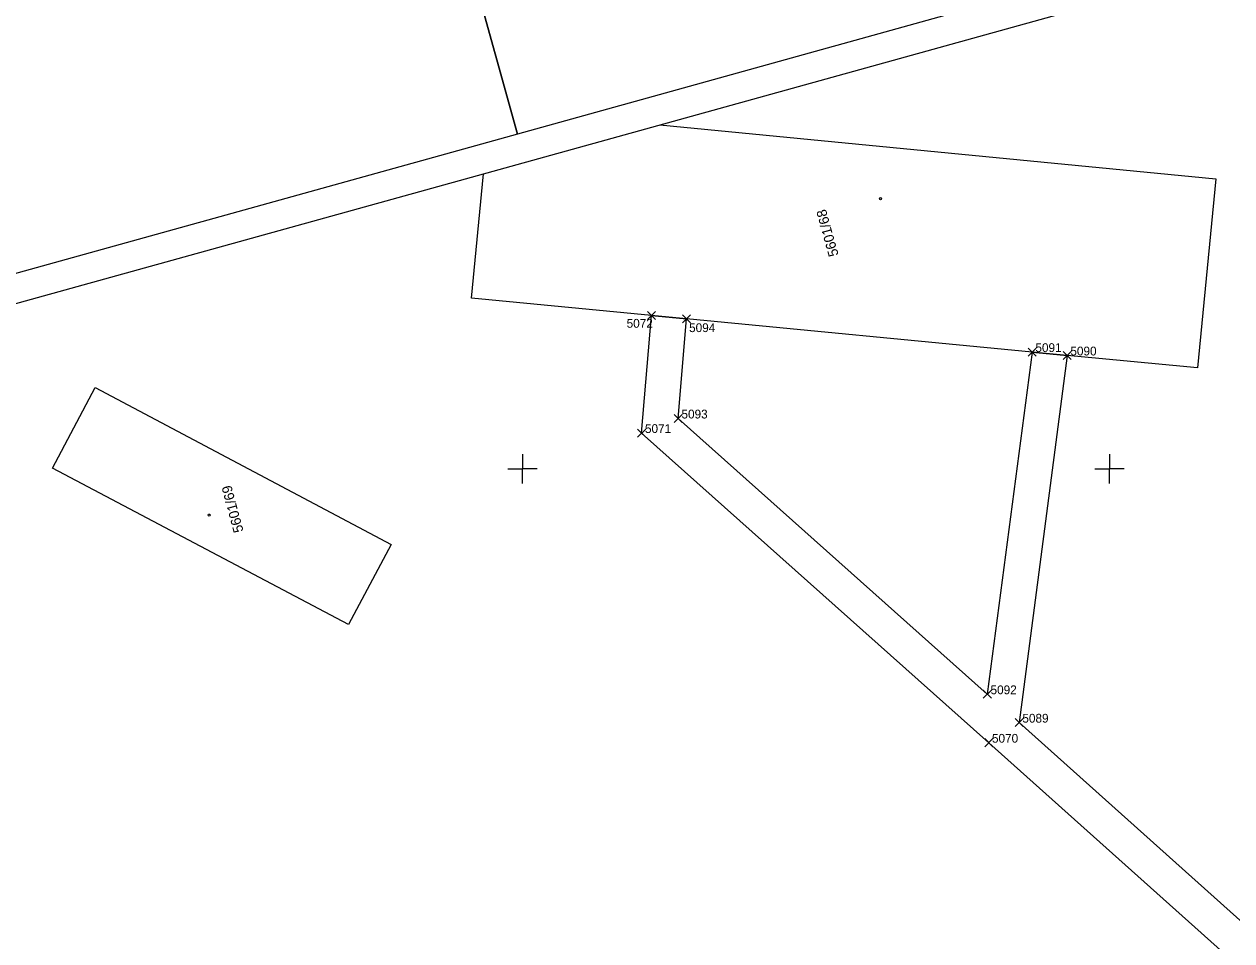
# Model space of a CAD drawing. Extents: x -821172 to -820632, y -1070921 to -1069931.
# Drawn here: x -821042.4 to -820939.6, y -1070140.2 to -1070062.1 of the extents above; entities that cross this region are included whole.
import ezdxf

# ---------------------------------------------------------------- set-up
doc = ezdxf.new("R2010")
doc.units = 0
for name, color, linetype in [('Ram', 7, 'Continuous'), ('Sit', 7, 'Continuous'), ('VB_bod_DZ', 7, 'Continuous'), ('Vrstva 52', 7, 'Continuous'), ('Vrstva 55', 7, 'Continuous'), ('Vrstva 57', 7, 'Continuous'), ('Vrstva 59', 7, 'Continuous')]:
    doc.layers.add(name, color=color, linetype=linetype)

msp = doc.modelspace()

# ---------------------------------------------------------------- linework, layer by layer
at = {"layer": 'Ram'}
msp.add_line((-820859.09, -1070034.8), (-821140.43, -1070112.97), dxfattribs=at)
for points in [[(-821000.43, -1070071.48), (-821028.54, -1069970.31), (-820885.46, -1069930.55), (-820857.35, -1070031.72)], [(-821028.54, -1069970.31), (-821000.43, -1070071.48)], [(-820857.35, -1070031.72), (-821000.43, -1070071.48)], [(-821000.43, -1070071.48), (-821143.51, -1070111.23)]]:
    msp.add_lwpolyline(points, dxfattribs=at)
at = {"layer": 'Sit'}
for p, q in [((-821000, -1070098.75), (-821000, -1070100)), ((-820950, -1070098.75), (-820950, -1070100)), ((-821001.25, -1070100), (-821000, -1070100)), ((-820998.75, -1070100), (-821000, -1070100)), ((-821000, -1070101.25), (-821000, -1070100)), ((-820951.25, -1070100), (-820950, -1070100)), ((-820948.75, -1070100), (-820950, -1070100)), ((-820950, -1070101.25), (-820950, -1070100))]:
    msp.add_line(p, q, dxfattribs=at)
at = {"layer": 'VB_bod_DZ'}
for p, q in [((-820989.35, -1070087.28), (-820988.66, -1070086.6)), ((-820988.66, -1070087.28), (-820989.35, -1070086.6)), ((-820986.36, -1070087.57), (-820985.68, -1070086.88)), ((-820985.68, -1070087.57), (-820986.36, -1070086.88)), ((-820956.93, -1070090.39), (-820956.24, -1070089.71)), ((-820956.24, -1070090.39), (-820956.93, -1070089.71)), ((-820953.94, -1070090.68), (-820953.25, -1070089.99)), ((-820953.25, -1070090.68), (-820953.94, -1070089.99)), ((-820987.07, -1070096.05), (-820986.39, -1070095.37)), ((-820986.39, -1070096.05), (-820987.07, -1070095.37)), ((-820990.19, -1070097.29), (-820989.5, -1070096.61)), ((-820989.5, -1070097.29), (-820990.19, -1070096.61)), ((-820960.74, -1070119.55), (-820960.05, -1070118.87)), ((-820960.05, -1070119.55), (-820960.74, -1070118.87)), ((-820958.03, -1070121.97), (-820957.34, -1070121.28)), ((-820957.34, -1070121.97), (-820958.03, -1070121.28)), ((-820960.62, -1070123.68), (-820959.93, -1070122.99)), ((-820959.93, -1070123.68), (-820960.62, -1070122.99))]:
    msp.add_line(p, q, dxfattribs=at)
at = {"layer": 'Vrstva 52'}
for p, q in [((-820989.01, -1070086.94), (-820986.02, -1070087.23)), ((-820956.59, -1070090.05), (-820960.4, -1070119.21)), ((-820956.59, -1070090.05), (-820953.6, -1070090.34)), ((-820953.6, -1070090.34), (-820957.69, -1070121.63))]:
    msp.add_line(p, q, dxfattribs=at)
for points in [[(-820843.48, -1070284.13), (-820843.93, -1070282.84), (-820847.81, -1070277.93), (-820871.73, -1070237.25), (-820885.29, -1070218.2), (-820887.54, -1070214.67), (-820897.96, -1070197.77), (-820903.32, -1070188.38), (-820912.12, -1070190.61), (-820919.97, -1070176.29), (-820926.49, -1070162.4), (-820934.28, -1070147.4), (-820935.96, -1070145.11), (-820960.28, -1070123.34), (-820989.85, -1070096.95), (-820989.01, -1070086.94)], [(-820960.4, -1070119.21), (-820986.73, -1070095.71), (-820986.02, -1070087.23)], [(-820905.06, -1070185.73), (-820910.61, -1070187.13), (-820917.29, -1070174.93), (-820923.8, -1070161.07), (-820931.72, -1070145.81), (-820933.72, -1070143.08), (-820957.69, -1070121.63)]]:
    msp.add_lwpolyline(points, dxfattribs=at)
at = {"layer": 'Vrstva 55'}
for points in [[(-820988.3, -1070070.68), (-820940.94, -1070075.3), (-820942.5, -1070091.4)], [(-820942.5, -1070091.4), (-820953.6, -1070090.34), (-820956.59, -1070090.05), (-820986.02, -1070087.23), (-820989.01, -1070086.94), (-821004.34, -1070085.47), (-821003.31, -1070074.87)], [(-821014.82, -1070113.27), (-821040.04, -1070099.95), (-821036.4, -1070093.07), (-821011.18, -1070106.44), (-821014.82, -1070113.27)]]:
    msp.add_lwpolyline(points, dxfattribs=at)
at = {"layer": 'Vrstva 59'}
for centre in [(-820969.49, -1070076.98), (-821026.69, -1070103.94)]:
    msp.add_circle(centre, 0.0875, dxfattribs=at)

# ---------------------------------------------------------------- texts
at = {"layer": 'VB_bod_DZ'}
for s, p in [(' 5072', (-820991.4, -1070087.98)), (' 5094', (-820986.08, -1070088.35)), (' 5091', (-820956.58, -1070090.05)), (' 5090', (-820953.6, -1070090.34)), (' 5093', (-820986.73, -1070095.71)), (' 5071', (-820989.84, -1070096.95)), (' 5092', (-820960.4, -1070119.21)), (' 5089', (-820957.69, -1070121.63)), (' 5070', (-820960.28, -1070123.34))]:
    msp.add_text(s, height=0.75, dxfattribs=at).set_placement(p)
at = {"layer": 'Vrstva 57'}
for s, rotation, p in [('5601/68', 105.5289, (-820973.06, -1070081.78)), ('5601/69', 105, (-821023.75, -1070105.31))]:
    msp.add_text(s, height=0.85, rotation=rotation, dxfattribs=at).set_placement(p)

doc.saveas('drawing.dxf')
